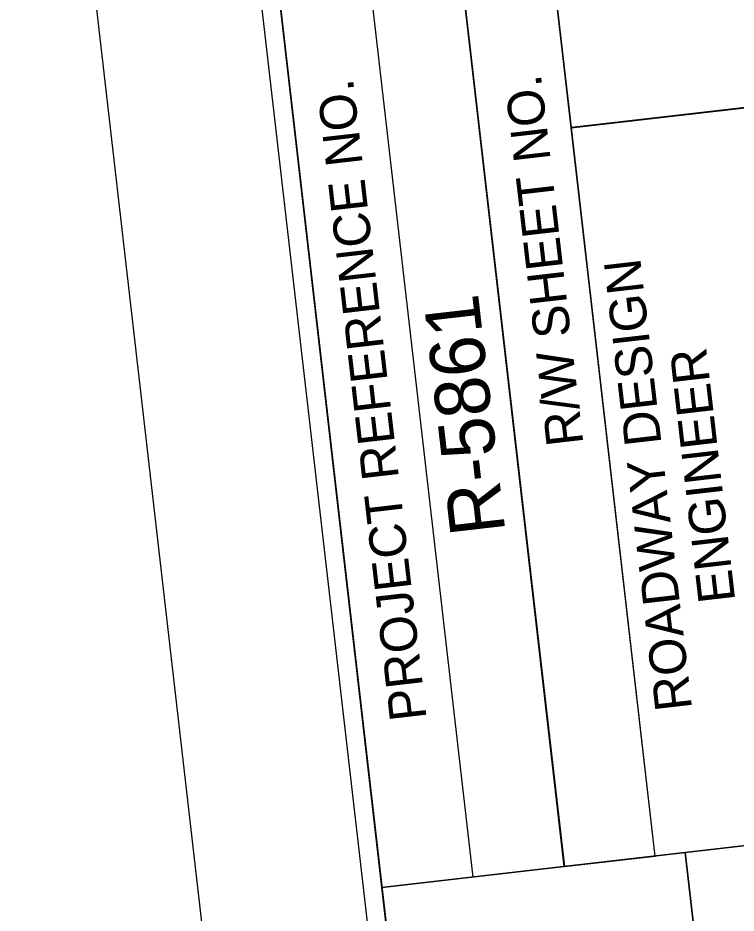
# Model space of a CAD drawing. Extents: x 477607 to 479438, y 495543 to 499482.
# Drawn here: x 477606.8 to 477704.9, y 497193.8 to 497316 of the extents above; entities that cross this region are included whole.
import ezdxf

# ---------------------------------------------------------------- set-up
doc = ezdxf.new("R2010")
doc.units = 0
for name, color, linetype in [('Prop Grid Mask', 7, 'Continuous'), ('Sheet Border Standard 30in CELL', 7, 'Continuous'), ('Sheet Cutting Line CELL', 7, 'Continuous'), ('Sheet Data Field CELL', 7, 'Continuous'), ('Sheet Layout Plan Border', 7, 'Continuous'), ('Sheet Plan CELL', 7, 'Continuous'), ('Sheet Plot Border Inside CELL', 7, 'Continuous'), ('Sheet Plot Border Outside CELL', 7, 'Continuous')]:
    doc.layers.add(name, color=color, linetype=linetype)

msp = doc.modelspace()

# ---------------------------------------------------------------- linework, layer by layer
at = {"layer": 'Prop Grid Mask'}
msp.add_lwpolyline([(477656.5, 497197.32), (477674.89, 497038.51), (477716.32, 497043.31), (477697.93, 497202.12)], close=True, dxfattribs=at)
at = {"layer": 'Sheet Border Standard 30in CELL'}
for p, q in [((477681.41, 497200.18), (477658.5, 497398.91)), ((477681.41, 497200.18), (477658.5, 497398.91)), ((477668.99, 497198.75), (477646.08, 497397.48)), ((477682.37, 497301), (477794.08, 497313.88)), ((477681.41, 497200.18), (477693.83, 497201.61))]:
    msp.add_line(p, q, dxfattribs=at)
for points in [[(477633.61, 497396.04), (477805.43, 495905.92), (478848.52, 496026.19), (478676.7, 497516.31)], [(477682.37, 497301), (477670.91, 497400.34), (477782.67, 497413.23), (477794.13, 497313.89)], [(477656.53, 497197.31), (477633.61, 497396.04), (477658.5, 497398.91), (477681.41, 497200.18)], [(477693.83, 497201.61), (477682.37, 497301), (477794.13, 497313.89), (477805.59, 497214.5)]]:
    msp.add_lwpolyline(points, close=True, dxfattribs=at)
at = {"layer": 'Sheet Cutting Line CELL'}
msp.add_line((477606.83, 497410.07), (477799.72, 495737.15), dxfattribs=at)
at = {"layer": 'Sheet Layout Plan Border'}
msp.add_lwpolyline([(478060.61, 495968.97), (478655.26, 496063.07), (478848.53, 496026.02), (478736, 497002.06), (478709.93, 496998.31), (478420.13, 496964.9), (478384.13, 497277.1), (478673.93, 497310.52), (478699.76, 497316.34), (478696.24, 497346.89), (478616.75, 497337.72), (478607.5, 497417.87), (478188.47, 497393.35), (477955.38, 497379.71), (477811.17, 497371.27), (477828.93, 497217.21), (477697.93, 497202.08), (477716.32, 497043.31), (477674.84, 497038.51), (477805.45, 495905.89)], close=True, dxfattribs=at)
msp.add_lwpolyline([(478060.61, 495968.97), (478655.26, 496063.07), (478848.53, 496026.02), (478736, 497002.06), (478709.93, 496998.31), (478420.13, 496964.9), (478384.13, 497277.1), (478673.93, 497310.52), (478699.76, 497316.34), (478696.24, 497346.89), (478616.75, 497337.72), (478607.5, 497417.87), (478188.47, 497393.35), (477955.38, 497379.71), (477811.17, 497371.27), (477828.93, 497217.21), (477697.93, 497202.08), (477716.32, 497043.31), (477674.84, 497038.51), (477805.45, 495905.89)], close=True, dxfattribs=at)
at = {"layer": 'Sheet Plan CELL'}
for p, q in [((477681.43, 497200.19), (477658.5, 497398.91)), ((477681.43, 497200.19), (477658.5, 497398.91)), ((477668.98, 497198.75), (477646.08, 497397.48)), ((477682.38, 497301.02), (477794.1, 497313.91)), ((477681.43, 497200.21), (477693.84, 497201.64)), ((477681.43, 497200.19), (477693.84, 497201.62))]:
    msp.add_line(p, q, dxfattribs=at)
for points in [[(477633.61, 497396.08), (477805.43, 495905.92), (478848.52, 496026.19), (478676.7, 497516.33)], [(478848.52, 496026.19), (477805.45, 495905.89), (477656.51, 497197.32), (477805.59, 497214.52), (477782.68, 497413.24), (478676.7, 497516.33)], [(477682.38, 497301.02), (477670.91, 497400.34), (477782.68, 497413.24), (477794.15, 497313.9)], [(477656.51, 497197.32), (477633.61, 497396.08), (477658.5, 497398.91), (477681.43, 497200.19)], [(477693.84, 497201.62), (477682.38, 497301.02), (477794.15, 497313.9), (477805.59, 497214.52)]]:
    msp.add_lwpolyline(points, close=True, dxfattribs=at)
at = {"layer": 'Sheet Plot Border Inside CELL'}
msp.add_lwpolyline([(477629.65, 497408.17), (477820.53, 495752.64), (478868.69, 495873.49), (478677.8, 497529.02)], close=True, dxfattribs=at)
at = {"layer": 'Sheet Plot Border Outside CELL'}
msp.add_lwpolyline([(477606.83, 497410.07), (477799.72, 495737.15), (478892.48, 495863.15), (478699.59, 497536.07)], close=True, dxfattribs=at)

# ---------------------------------------------------------------- texts
at = {"layer": 'Sheet Border Standard 30in CELL'}
for s, height, p in [('R/W SHEET NO.', 5.0001, (477684.02, 497257.86)), ('PROJECT REFERENCE NO.', 5.0001, (477662.63, 497220.36)), ('ROADWAY DESIGN', 5.0001, (477698.86, 497221.72)), ('ENGINEER', 5, (477704.76, 497236.44))]:
    msp.add_text(s, height=height, rotation=96.5773, dxfattribs=at).set_placement(p)
at = {"layer": 'Sheet Data Field CELL'}
msp.add_text('R-5861', height=7.5, rotation=96.5773, dxfattribs=at).set_placement((477673.39, 497245.84))
at = {"layer": 'Sheet Plan CELL'}
for s, height, p in [('R/W SHEET NO.', 5.0001, (477684.03, 497257.87)), ('PROJECT REFERENCE NO.', 5.0001, (477662.64, 497220.37)), ('ROADWAY DESIGN', 5.0001, (477698.87, 497221.71)), ('ENGINEER', 5, (477704.76, 497236.47))]:
    msp.add_text(s, height=height, rotation=96.5773, dxfattribs=at).set_placement(p)

doc.saveas('drawing.dxf')
